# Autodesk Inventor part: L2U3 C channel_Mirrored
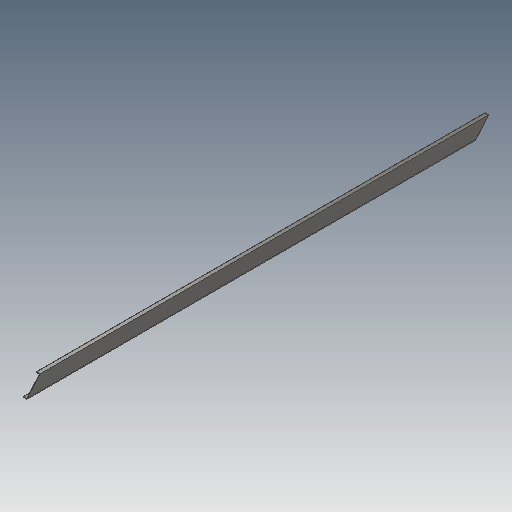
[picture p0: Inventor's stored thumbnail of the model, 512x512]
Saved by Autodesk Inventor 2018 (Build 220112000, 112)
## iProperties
Created: 2018-02
Part Number: L2U3 C channel_Mirrored
Material: Steel, Mild
Document SubType Name: Modeling
Designer: STK
Density: 7.85 g/cm^3
Appearance: Semi-Polished
Author: STK
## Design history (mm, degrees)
derived "L2U3 C channel.ipt"
feature "Solid1::L2U3 C channel.ipt" dims "d0" = 10
tag "TaggingFeature1"
body "Solid1"
